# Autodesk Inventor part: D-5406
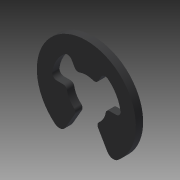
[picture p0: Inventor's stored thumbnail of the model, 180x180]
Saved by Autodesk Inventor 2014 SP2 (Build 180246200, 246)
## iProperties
Created: 2020-01
Part Number: D-5406
Material: Generic
Catalog Web Link: www.cadenas.de
Description: Piston Rod Clevis for Original Line Cylinders - Retaining Ring-
Vendor: BIMBA
Document SubType Name: Modeling
Designer: psadmin
Manufacturer: BIMBA
Mass: 0.0293732 g
Surface Area: 1.16896 cm^2
Volume: 0.0293732 cm^3
Density: 1 g/cm^3
Appearance: PSOLRGB-84-84-84
Category: PARTsolutions
Company: BIMBA
Title: D-5406
Author: Cadenas PARTsolutions
PSOL_IDENT_0: {$CADENAS_DATA\23d-libs\bimba\bimba_brand\bimba_imperial\bimba_full_line\original_line_cylinders\acc
PSOL_IDENT_1: essories\piston_rod_clevis_rr.prj},208 {VTYP=3D},{NB=D-5406},{LINA=D-5406},{NN=Piston Rod Clevis for
PSOL_IDENT_2: Original Line Cylinders - Retaining Ring},{DATE=23.12.2019 10:36:52},{GEOMDATE=06.12.2012 07:18:40}
PSOL_IDENT_3: ,{VERSION=},{LINEID=20},{WBVAR=},{WBNUMERIC=}  {NB=D-5406},{LINA=D-5406},{KT=DUMMY},{PN=D-5406},{D=0
PSOL_IDENT_4: .37500000},{D1=0.14850000},{D2=0.26175},{L=0.02750000},{COLOR=0.75,0.75,0.75,0.00}
NN: Piston Rod Clevis for Original Line Cylinders - Retaining Ring
NB: D-5406
NBSYN: $PN.
LINA: D-5406
PN: D-5406
D: 0.375
D1: 0.1485
L: 0.0275
SUPPLIER: BIMBA
ARTICLENO: D-5406
BOMINFO: D-5406
CREATOR: CADENAS GmbH
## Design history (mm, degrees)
sketch "Sketch_1"
  geometry: L1 (-2.022, -3.502)-(-1.116, -1.933); L2 (-2.231, 0)-(-2.847, 0); L3 (-1.423, 2.465)-(-1.116, 1.933); L4 (1.116, 1.933)-(1.423, 2.465); L5 (2.847, 0)-(2.231, 0); L6 (1.116, -1.933)-(2.022, -3.502); A1 r 4.762 centre (0, 0) between (3.019, -3.683) and (-3.019, -3.683); A2 r 0.665 centre (-2.597, -3.169) between (-3.019, -3.683) and (-2.022, -3.502); A3 r 0.377 centre (-1.442, -1.744) between (-1.116, -1.933) and (-1.202, -1.453); A4 r 1.886 centre (0, 0) between (-1.86, -0.314) and (-1.202, -1.453); A5 r 0.377 centre (-2.231, -0.377) between (-1.86, -0.314) and (-2.231, 0); A6 r 0.443 centre (-2.847, 0.443) between (-3.285, 0.511) and (-2.847, 0); A7 r 3.324 centre (0, 0) between (-2.085, 2.589) and (-3.285, 0.511); A8 r 0.443 centre (-1.807, 2.244) between (-1.423, 2.465) and (-2.085, 2.589); A9 r 0.377 centre (-0.789, 2.121) between (-1.116, 1.933) and (-0.658, 1.768); A10 r 1.886 centre (0, 0) between (0.658, 1.768) and (-0.658, 1.768); A11 r 0.377 centre (0.789, 2.121) between (0.658, 1.768) and (1.116, 1.933); A12 r 0.443 centre (1.807, 2.244) between (2.085, 2.589) and (1.423, 2.465); A13 r 3.324 centre (0, 0) between (3.285, 0.511) and (2.085, 2.589); A14 r 0.443 centre (2.847, 0.443) between (2.847, 0) and (3.285, 0.511); A15 r 0.377 centre (2.231, -0.377) between (2.231, 0) and (1.86, -0.314); A16 r 1.886 centre (0, 0) between (1.202, -1.453) and (1.86, -0.314); A17 r 0.377 centre (1.442, -1.744) between (1.202, -1.453) and (1.116, -1.933); A18 r 0.665 centre (2.597, -3.169) between (2.022, -3.502) and (3.019, -3.683)
  constraints: 36 point on circle, 18 centre point, 12 end point
extrude "Extrusion1" join sketch "Sketch_1" stored distance "d0" = 0.6985; taper "d1" = 0 deg
node "RR_XY"
node "RR_YZ"
node "RR_ZX"
node "RR_X"
node "RR_Y"
node "RR_Z"
node "RR_Center"
body "Solid1"
